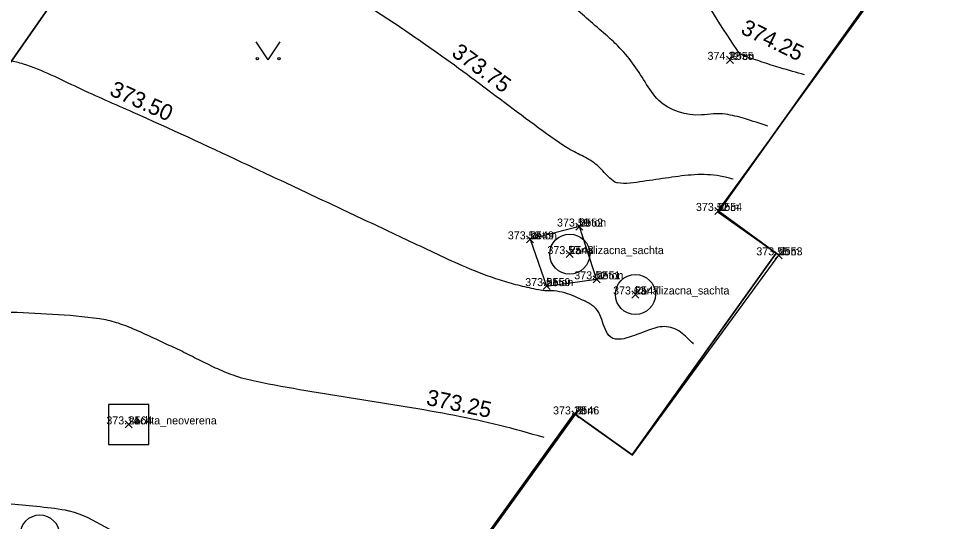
# Model space of a CAD drawing. Extents: x -400488 to -400124, y -1251493 to -1251223.
# Drawn here: x -400361.06 to -400338.08, y -1251319.82 to -1251307.23 of the extents above; entities that cross this region are included whole.
import ezdxf

# ---------------------------------------------------------------- set-up
doc = ezdxf.new("R2010")
doc.units = 0
for name, color, linetype in [('Level 20', 7, 'Continuous'), ('Level 21', 7, 'Continuous'), ('Level 22', 7, 'Continuous'), ('Level 23', 7, 'Continuous'), ('Level 31', 7, 'Continuous'), ('Level 34', 7, 'Continuous'), ('Level 36', 7, 'Continuous'), ('Level 49', 7, 'Continuous'), ('Level 52', 7, 'Continuous'), ('Level 60', 7, 'Continuous'), ('Level 63', 7, 'Continuous')]:
    doc.layers.add(name, color=color, linetype=linetype)

msp = doc.modelspace()

# ---------------------------------------------------------------- linework, layer by layer
at = {"layer": 'Level 20'}
for p, q in [((-400343.378, -1251308.358), (-400343.202, -1251308.182)), ((-400343.202, -1251308.358), (-400343.378, -1251308.182)), ((-400343.668, -1251312.138), (-400343.492, -1251311.962)), ((-400343.492, -1251312.138), (-400343.668, -1251311.962)), ((-400347.138, -1251312.528), (-400346.962, -1251312.352)), ((-400346.962, -1251312.528), (-400347.138, -1251312.352)), ((-400348.368, -1251312.848), (-400348.192, -1251312.672)), ((-400348.192, -1251312.848), (-400348.368, -1251312.672)), ((-400347.378, -1251313.218), (-400347.202, -1251313.042)), ((-400347.202, -1251313.218), (-400347.378, -1251313.042)), ((-400342.158, -1251313.248), (-400341.982, -1251313.072)), ((-400341.982, -1251313.248), (-400342.158, -1251313.072)), ((-400347.958, -1251314.018), (-400347.782, -1251313.842)), ((-400347.782, -1251314.018), (-400347.958, -1251313.842)), ((-400346.708, -1251313.848), (-400346.532, -1251313.672)), ((-400346.532, -1251313.848), (-400346.708, -1251313.672)), ((-400345.738, -1251314.228), (-400345.562, -1251314.052)), ((-400345.562, -1251314.228), (-400345.738, -1251314.052)), ((-400347.238, -1251317.228), (-400347.062, -1251317.052)), ((-400347.062, -1251317.228), (-400347.238, -1251317.052)), ((-400358.398, -1251317.478), (-400358.222, -1251317.302)), ((-400358.222, -1251317.478), (-400358.398, -1251317.302))]:
    msp.add_line(p, q, dxfattribs=at)
at = {"layer": 'Level 31'}
msp.add_lwpolyline([(-400347.05, -1251312.44), (-400348.28, -1251312.76), (-400347.87, -1251313.93), (-400346.62, -1251313.76), (-400347.05, -1251312.44)], dxfattribs=at)
at = {"layer": 'Level 34'}
for points in [[(-400343.58, -1251312.05), (-400339.12, -1251305.887), (-400338.95, -1251305.64), (-400338.78, -1251305.45), (-400332.06, -1251310.22), (-400331.92, -1251310.33)], [(-400348.66, -1251326.37), (-400352.04, -1251323.95), (-400347.15, -1251317.14), (-400345.723, -1251318.156), (-400342.07, -1251313.16), (-400343.58, -1251312.05)]]:
    msp.add_lwpolyline(points, dxfattribs=at)
at = {"layer": 'Level 36'}
for q in [(-400355.126, -1251307.821), (-400354.526, -1251307.821)]:
    msp.add_line((-400354.826, -1251308.271), q, dxfattribs=at)
for centre in [(-400355.096, -1251308.241), (-400354.556, -1251308.241)]:
    msp.add_circle(centre, 0.03, dxfattribs=at)
msp.add_arc((-400360.53, -1251320.16), 0.5, 0, 180, dxfattribs=at)
at = {"layer": 'Level 49'}
for points in [[(-400341.424, -1251308.644), (-400342.03, -1251308.471), (-400342.935, -1251308.167), (-400343.035, -1251308.116), (-400343.078, -1251308.067), (-400343.099, -1251308.037), (-400345.18, -1251305.198), (-400345.34, -1251305.017), (-400345.356, -1251304.985), (-400345.46, -1251304.596), (-400345.506, -1251304.19), (-400345.565, -1251303.782), (-400345.707, -1251303.386), (-400346.407, -1251302.529), (-400346.859, -1251302.233), (-400347.364, -1251302.048), (-400348.033, -1251302.008), (-400348.705, -1251302.119), (-400349.377, -1251302.256), (-400350.045, -1251302.295), (-400350.075, -1251302.289), (-400350.088, -1251302.276), (-400350.569, -1251302.009), (-400351.077, -1251301.774), (-400351.583, -1251301.532), (-400352.06, -1251301.242), (-400353.809, -1251299.847), (-400354.617, -1251299.076), (-400355.383, -1251298.255), (-400356.062, -1251297.423), (-400356.69, -1251296.554), (-400356.986, -1251296.11), (-400357.268, -1251295.659), (-400357.802, -1251294.742), (-400357.815, -1251294.706), (-400357.816, -1251294.705), (-400358.039, -1251294.541), (-400358.38, -1251294.415), (-400358.42, -1251294.414), (-400359.074, -1251294.476), (-400359.403, -1251294.543), (-400359.728, -1251294.621), (-400360.224, -1251294.761), (-400360.717, -1251294.912)], [(-400342.338, -1251309.931), (-400342.926, -1251309.741), (-400343.403, -1251309.632), (-400343.7, -1251309.621), (-400343.998, -1251309.649), (-400345.067, -1251309.285), (-400345.407, -1251308.822), (-400345.721, -1251308.352), (-400346.087, -1251307.924), (-400346.398, -1251307.637), (-400347.239, -1251306.906), (-400348.093, -1251306.191), (-400349.765, -1251304.717), (-400349.777, -1251304.701), (-400351.677, -1251303.581), (-400351.722, -1251303.572), (-400351.728, -1251303.567), (-400352.566, -1251303.179), (-400353.445, -1251302.853), (-400354.315, -1251302.505), (-400355.121, -1251302.048), (-400355.747, -1251301.563), (-400356.101, -1251301.255), (-400356.253, -1251301.223), (-400356.406, -1251301.202), (-400356.712, -1251301.168), (-400357.324, -1251301.088), (-400358.547, -1251300.933), (-400364.448, -1251300.144)], [(-400343.209, -1251311.253), (-400343.532, -1251311.179), (-400344.172, -1251311.146), (-400344.816, -1251311.218), (-400345.461, -1251311.313), (-400346.105, -1251311.346), (-400346.116, -1251311.344), (-400346.287, -1251311.229), (-400346.431, -1251311.087), (-400346.569, -1251310.941), (-400346.723, -1251310.818), (-400346.9, -1251310.714), (-400347.083, -1251310.62), (-400347.265, -1251310.526), (-400347.439, -1251310.419), (-400348.288, -1251309.813), (-400349.125, -1251309.188), (-400349.962, -1251308.561), (-400350.811, -1251307.952), (-400352.125, -1251307.062), (-400352.799, -1251306.642), (-400353.489, -1251306.24), (-400355.033, -1251305.509), (-400356.643, -1251304.939), (-400357.283, -1251304.758), (-400357.939, -1251304.623), (-400358.583, -1251304.46), (-400359.188, -1251304.2), (-400359.21, -1251304.186), (-400359.228, -1251304.175), (-400361.036, -1251303.648), (-400361.979, -1251303.582), (-400362.918, -1251303.549), (-400362.946, -1251303.551), (-400363.275, -1251303.682), (-400363.596, -1251303.817), (-400364.226, -1251304.092), (-400365.474, -1251304.643), (-400368.248, -1251305.829)], [(-400348.13, -1251314.015), (-400348.581, -1251313.91), (-400349.024, -1251313.784), (-400349.884, -1251313.458), (-400351.284, -1251312.811), (-400352.678, -1251312.155), (-400354.07, -1251311.497), (-400355.466, -1251310.843), (-400358.195, -1251309.587), (-400359.564, -1251308.973), (-400360.94, -1251308.376), (-400361.287, -1251308.297), (-400361.654, -1251308.313), (-400362.024, -1251308.382), (-400362.38, -1251308.461), (-400362.61, -1251308.513), (-400362.839, -1251308.576), (-400363.294, -1251308.73), (-400364.197, -1251309.13), (-400365.983, -1251310.108), (-400367.769, -1251310.974), (-400368.672, -1251311.234), (-400369.128, -1251311.297), (-400369.357, -1251311.31), (-400369.587, -1251311.308), (-400370.466, -1251311.167), (-400371.752, -1251310.724)], [(-400347.932, -1251317.716), (-400349.041, -1251317.416), (-400350.16, -1251317.169), (-400351.4, -1251316.95), (-400352.643, -1251316.75), (-400353.885, -1251316.547), (-400355.123, -1251316.318), (-400355.703, -1251316.162), (-400356.138, -1251315.979), (-400356.561, -1251315.774), (-400356.981, -1251315.562), (-400357.408, -1251315.363), (-400358.207, -1251314.997), (-400358.615, -1251314.845), (-400358.825, -1251314.789), (-400359.039, -1251314.751), (-400360.213, -1251314.639), (-400361.389, -1251314.581), (-400363.153, -1251314.532), (-400363.741, -1251314.512), (-400364.638, -1251314.485), (-400365.536, -1251314.466), (-400366.433, -1251314.446), (-400367.33, -1251314.416), (-400367.882, -1251314.331), (-400368.415, -1251314.147), (-400369.451, -1251313.617), (-400370.485, -1251313.098), (-400371.017, -1251312.928), (-400372.971, -1251312.64)], [(-400344.201, -1251315.376), (-400344.207, -1251315.37), (-400344.359, -1251315.224), (-400344.523, -1251315.082), (-400344.924, -1251314.945), (-400345.35, -1251315.044), (-400345.783, -1251315.202), (-400346.202, -1251315.243), (-400346.214, -1251315.239), (-400346.378, -1251315.059), (-400346.473, -1251314.824), (-400346.567, -1251314.59), (-400346.728, -1251314.413), (-400346.972, -1251314.278), (-400347.223, -1251314.167), (-400347.748, -1251314.049), (-400347.844, -1251314.049), (-400348.13, -1251314.015)], [(-400352.293, -1251323.278), (-400352.826, -1251323.097), (-400352.844, -1251323.089), (-400354.58, -1251322.223), (-400356.287, -1251321.302), (-400358.007, -1251320.393), (-400358.886, -1251319.963), (-400359.784, -1251319.561), (-400359.802, -1251319.557), (-400360.521, -1251319.456), (-400361.243, -1251319.387), (-400361.966, -1251319.353), (-400362.686, -1251319.354), (-400362.706, -1251319.359), (-400363.04, -1251319.588), (-400363.343, -1251319.84), (-400363.891, -1251320.382), (-400364.419, -1251320.929), (-400364.995, -1251321.421), (-400366.014, -1251322.099), (-400366.527, -1251322.437), (-400367.024, -1251322.796), (-400367.495, -1251323.197), (-400367.955, -1251323.654), (-400368.388, -1251324.135), (-400368.82, -1251324.624), (-400370.184, -1251324.602), (-400371.084, -1251324.11), (-400371.985, -1251323.601), (-400372.84, -1251323.028), (-400374.376, -1251321.785), (-400375.093, -1251321.106), (-400376.539, -1251320.249), (-400376.957, -1251320.548), (-400377.775, -1251321.215), (-400378.615, -1251321.804), (-400379.061, -1251322.005), (-400379.52, -1251322.108)]]:
    msp.add_spline(points, degree=3, dxfattribs=at)
at = {"layer": 'Level 52'}
for centre in [(-400347.29, -1251313.13), (-400345.65, -1251314.14)]:
    msp.add_circle(centre, 0.5, dxfattribs=at)
at = {"layer": 'Level 60'}
msp.add_lwpolyline([(-400358.81, -1251317.89), (-400357.81, -1251317.89), (-400357.81, -1251316.89), (-400358.81, -1251316.89)], close=True, dxfattribs=at)
at = {"layer": 'Level 63'}
for p, q in [((-400352.67, -1251296), (-400379.03, -1251333.83)), ((-400379.03, -1251333.83), (-400352.67, -1251296)), ((-400339.07, -1251305.73), (-400343.58, -1251312.08)), ((-400343.58, -1251312.08), (-400339.07, -1251305.73)), ((-400343.58, -1251312.08), (-400342.13, -1251313.11)), ((-400342.13, -1251313.11), (-400343.58, -1251312.08)), ((-400342.13, -1251313.11), (-400345.73, -1251318.15)), ((-400345.73, -1251318.15), (-400342.13, -1251313.11)), ((-400347.18, -1251317.12), (-400352.07, -1251323.91)), ((-400352.07, -1251323.91), (-400347.18, -1251317.12)), ((-400345.73, -1251318.15), (-400347.18, -1251317.12)), ((-400347.18, -1251317.12), (-400345.73, -1251318.15))]:
    msp.add_line(p, q, dxfattribs=at)

# ---------------------------------------------------------------- texts
at = {"layer": 'Level 21'}
for s, p in [('2555', (-400343.29, -1251308.27)), ('2554', (-400343.58, -1251312.05)), ('2552', (-400347.05, -1251312.44)), ('2549', (-400348.28, -1251312.76)), ('2548', (-400347.29, -1251313.13)), ('2553', (-400342.07, -1251313.16)), ('2551', (-400346.62, -1251313.76)), ('2550', (-400347.87, -1251313.93)), ('2547', (-400345.65, -1251314.14)), ('2546', (-400347.15, -1251317.14)), ('2564', (-400358.31, -1251317.39))]:
    msp.add_text(s, height=0.2, dxfattribs=at).set_placement(p)
at = {"layer": 'Level 22'}
for s, p in [('teren', (-400343.29, -1251308.27)), ('dom', (-400343.58, -1251312.05)), ('beton', (-400347.05, -1251312.44)), ('beton', (-400348.28, -1251312.76)), ('kanalizacna_sachta', (-400347.29, -1251313.13)), ('dom', (-400342.07, -1251313.16)), ('beton', (-400346.62, -1251313.76)), ('beton', (-400347.87, -1251313.93)), ('kanalizacna_sachta', (-400345.65, -1251314.14)), ('dom', (-400347.15, -1251317.14)), ('sachta_neoverena', (-400358.31, -1251317.39))]:
    msp.add_text(s, height=0.2, dxfattribs=at).set_placement(p)
at = {"layer": 'Level 23'}
for s, p in [('374.22', (-400343.848, -1251308.27)), ('373.52', (-400344.138, -1251312.05)), ('373.59', (-400347.608, -1251312.44)), ('373.58', (-400348.838, -1251312.76)), ('373.57', (-400347.848, -1251313.13)), ('373.55', (-400342.629, -1251313.16)), ('373.52', (-400347.178, -1251313.76)), ('373.51', (-400348.403, -1251313.93)), ('373.63', (-400346.208, -1251314.14)), ('373.28', (-400347.708, -1251317.14)), ('373.14', (-400358.868, -1251317.39))]:
    msp.add_text(s, height=0.2, dxfattribs=at).set_placement(p)
at = {"layer": 'Level 49'}
for s, rotation, p in [('374.25', 334.0611, (-400343.045, -1251307.598)), ('373.75', 323.7951, (-400350.268, -1251308.152)), ('373.50', 335.6561, (-400358.812, -1251309.144)), ('373.25', 348.2997, (-400350.895, -1251316.898))]:
    msp.add_text(s, height=0.4, rotation=rotation, dxfattribs=at).set_placement(p)

doc.saveas('drawing.dxf')
